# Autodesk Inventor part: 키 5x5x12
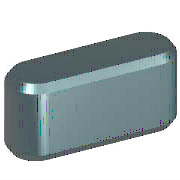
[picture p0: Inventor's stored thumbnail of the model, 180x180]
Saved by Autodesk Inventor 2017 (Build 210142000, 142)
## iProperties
IsCustomPart: 1
Created: 2012-02
Part Number: 키 5x5x12
Material: 강철, 연강
Description: 키 및 해당 키홈
Document SubType Name: Modeling
Standard: KS B 1311
Designer: mduedu
Standards Organization: KS
Language: ko-KR
Size Designation: 5 x 5 x 12
Categories: <MemberInstance><Categories><Category DisplayName="샤프트 부품" InternalName="7f7aeb1f-a693-4053-b835-cee3144e0d98" Mnemonic="SHFT"><Category DisplayName="키" Interna
Density: 1 g/cm^3
Appearance: Yellow
Author: mduedu
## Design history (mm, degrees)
sketch "스케치1"
  geometry: L1 (2.5, 2.5)-(9.5, 2.5); L2 (9.5, -2.5)-(2.5, -2.5); L3 (0, 9.4)-(0, -7.4) reference; L4 (-5, 0)-(30, 0) reference; L5 (12, 0)-(12, 7); A1 r 2.5 centre (2.5, 0) between (2.5, 2.5) and (2.5, -2.5); A2 r 2.5 centre (9.5, 0) between (9.5, -2.5) and (9.5, 2.5)
  constraints: 6 end point, 5 point on circle, 4 tangent, 3 point on line, 2 centre point, 1 horizontal, 1 parallel, 1 perpendicular
  dimensions: "d0" = 2.5 radius of A1 (= 0.5 x PB); "d13" = 2.5 radius of A2 (= 0.5 x PB); "d14" = 12 distance between parallel lines of L5 L3 (= NLG)
extrude "본체1" new body sketch "스케치1" taper "d3" = 0 deg; stored distance "d4" = 10
workplane "Work Plane3"
body "Solid1"
workplane "Work Plane1"
workplane "Work Plane2"
chamfer "모따기1" distance "d8" = 0.4 (= PHH); stored, may be unused: second distance "d9" = 0.4 (= PHH), angle "d15" = 45 deg
other parameters: "d1" = -3 (= -PNT), "d2" = 2 (= PH - PNT), "NLG" = 12 [user parameter; used in 3 equation terms], "PB" = 5 [user parameter; used in 2 equation terms], "PNT" = 3 [user parameter; used in 2 equation terms], "PH" = 5 [user parameter; used in 1 equation term], "PHH" = 0.4 [user parameter; used in 2 equation terms], "d10" = 0, "d16" = 0, "d17" = 0, "d18" = 0, "WDMIN" = 12 [user parameter], "PLB2" = 12 (= NLG) [user parameter], "WDMAX" = 17 [user parameter], "PLB1" = 12 (= NLG) [user parameter], "RR" = 0.16 [user parameter], "PUEB" = 2.3 [user parameter]
